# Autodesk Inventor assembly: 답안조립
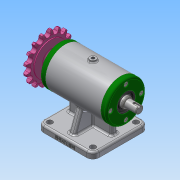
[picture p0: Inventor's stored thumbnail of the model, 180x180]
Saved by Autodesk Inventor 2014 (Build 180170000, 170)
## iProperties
Created: 2019-06
Part Number: 답안조립
Document SubType Name: Assembly
Designer: NET
Author: NET
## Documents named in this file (11)
- C:\Users\NET\Desktop\490604V1035\답안조립.iam
- C:\Users\NET\Desktop\490604V1035\답안본체.ipt
- C:\Users\NET\Desktop\490604V1035\축.ipt
- C:\Users\NET\Desktop\490604V1035\키 4x4x12.ipt
- C:\Users\NET\Desktop\490604V1035\베어링 6203.ipt
- C:\Users\NET\Desktop\490604V1035\커버.ipt
- C:\Users\NET\Desktop\490604V1035\오일 실 17 30 5.ipt
- C:\Users\NET\Desktop\490604V1035\스프로킷.ipt
- C:\Users\NET\Desktop\490604V1035\평와셔.ipt
- C:\Users\NET\Desktop\490604V1035\스프링와셔.ipt
- C:\Users\NET\Desktop\490604V1035\볼트 M4.ipt
